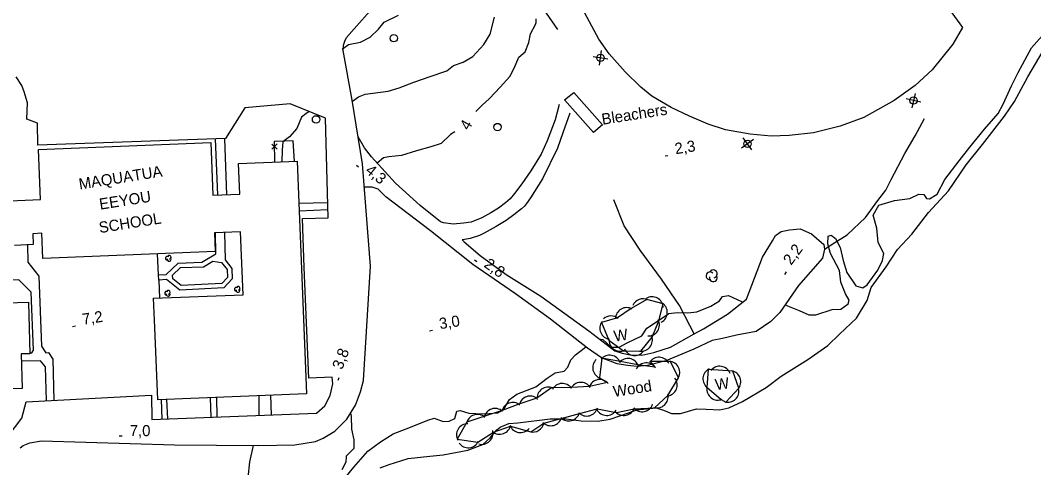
# Model space of a CAD drawing. Extents: x 646142 to 649934, y 5874075 to 5876351.
# Drawn here: x 647111.3 to 647384.4, y 5874421.5 to 5874542.2 of the extents above; entities that cross this region are included whole.
import ezdxf

# ---------------------------------------------------------------- set-up
doc = ezdxf.new("R2010")
doc.units = 0
for name, color, linetype in [('Niveau 19', 7, 'Continuous'), ('Niveau 2', 7, 'Continuous'), ('Niveau 22', 7, 'Continuous'), ('Niveau 3', 7, 'Continuous'), ('Niveau 31', 7, 'Continuous'), ('Niveau 36', 7, 'Continuous'), ('Niveau 37', 7, 'Continuous'), ('Niveau 4', 7, 'Continuous'), ('Niveau 44', 7, 'Continuous'), ('Niveau 56', 7, 'Continuous')]:
    doc.layers.add(name, color=color, linetype=linetype)

msp = doc.modelspace()

# ---------------------------------------------------------------- linework, layer by layer
at = {"layer": 'Niveau 19'}
for points in [[(647111.21, 5874426.85), (647112.01, 5874427.53), (647113.89, 5874428.24), (647116.95, 5874428.79), (647152.82, 5874427.71), (647175.49, 5874427.53), (647185.24, 5874427.7), (647190.8, 5874428.64), (647192.85, 5874429.47), (647196.05, 5874431.41), (647199.29, 5874434.63), (647201.59, 5874438.42), (647202.93, 5874442), (647203.75, 5874445.03), (647205.62, 5874475.91), (647203.48, 5874503.48), (647200.68, 5874520.68), (647198.25, 5874534.01), (647198.37, 5874535.49), (647198.72, 5874536.6), (647199.2, 5874537.54), (647208.24, 5874547.87)], [(647108, 5874430.06), (647111.68, 5874434.89), (647112.83, 5874439.28), (647146.62, 5874441.13), (647146.76, 5874434.51), (647191.12, 5874436.23), (647193.33, 5874438.25), (647194.77, 5874440.96), (647195.48, 5874444.13), (647195.31, 5874445.97), (647189.03, 5874445.68), (647187.8, 5874475.49), (647187.33, 5874488.7), (647194.2, 5874488.92), (647193.55, 5874515.82), (647184.02, 5874519.69), (647171.75, 5874518.55), (647166.58, 5874510.28), (647116.05, 5874508.52), (647115.9, 5874514.41), (647113.04, 5874515.54), (647113.2, 5874519.95), (647112.33, 5874522.88), (647111.68, 5874524.61), (647110.14, 5874526.97)], [(647256.44, 5874519.47), (647255.4, 5874515.38), (647253.28, 5874509.64), (647251.63, 5874506.12), (647248.83, 5874501.63), (647246.41, 5874498.06), (647244.46, 5874495.48), (647243.26, 5874494.02), (647242.01, 5874492.94), (647240.17, 5874491.5), (647238.07, 5874490.23), (647235.63, 5874488.96), (647232.73, 5874487.79), (647230.66, 5874487.45), (647227.95, 5874487.23), (647225.31, 5874487.61), (647224.5, 5874487.81), (647219.02, 5874492.21), (647212.38, 5874498.3), (647205.88, 5874505.35), (647204.05, 5874507.77), (647202.29, 5874510.8)], [(647259.34, 5874517.1), (647257.48, 5874511.86), (647256.06, 5874507.73), (647251.99, 5874499.41), (647248.76, 5874494.33), (647247.67, 5874492.78), (647247.12, 5874492.08), (647246.37, 5874491.36), (647244.26, 5874489.69), (647242.24, 5874488.18), (647239.54, 5874486.54), (647236.28, 5874484.74), (647235.02, 5874484.15), (647232.53, 5874483.32), (647230.94, 5874483.09), (647230.37, 5874482.97), (647230.91, 5874482.41), (647235.16, 5874478.77), (647242.19, 5874473.66), (647251.54, 5874467.82), (647258.05, 5874463.13), (647264.45, 5874458.42), (647271.51, 5874453.07), (647273.47, 5874452.43), (647275.65, 5874451.94), (647278.74, 5874451.88), (647282, 5874452.56), (647286.47, 5874454.07), (647292.88, 5874457.61), (647295.35, 5874458.97), (647301.83, 5874462.93), (647307, 5874467), (647311.31, 5874478.33)], [(647311.31, 5874478.33), (647313.94, 5874482.75), (647314.76, 5874484.12), (647316.31, 5874485.22), (647318.52, 5874485.68), (647321.45, 5874485.96), (647324.44, 5874484.6), (647327.81, 5874481.73), (647327.94, 5874480.44), (647327.47, 5874478.02), (647320.98, 5874470.63), (647315.9, 5874463.37), (647313.53, 5874461), (647309.54, 5874458.23), (647304.3, 5874457.24), (647300.47, 5874456.39), (647297.67, 5874455.88), (647292.81, 5874453.5), (647285.18, 5874450.38), (647280.32, 5874449.07), (647277.51, 5874448.79), (647274.86, 5874449.13), (647272.09, 5874449.57), (647267.9, 5874451.17), (647264.08, 5874453.76), (647254.17, 5874461.56), (647244.71, 5874468.45), (647233.26, 5874476.33), (647221.82, 5874485.39), (647209.77, 5874494.62), (647207.67, 5874496.66), (647206.08, 5874497.21), (647205.62, 5874497.17), (647203.97, 5874497.17)]]:
    msp.add_lwpolyline(points, dxfattribs=at)
at = {"layer": 'Niveau 2'}
for points in [[(647198.03, 5874534.4), (647199.69, 5874535.62), (647202.98, 5874536.3), (647205.56, 5874537.61), (647207.76, 5874539.83), (647209.34, 5874541.64), (647213.16, 5874543.6)], [(647200.82, 5874520.38), (647202.41, 5874521.55), (647204.2, 5874522.28), (647210.41, 5874523.08), (647213.41, 5874523.97), (647217.29, 5874525.52), (647221.75, 5874526.99), (647226.2, 5874528.53), (647228, 5874530.02), (647230.65, 5874530.94), (647233.2, 5874532.38), (647236.17, 5874535.66), (647237.92, 5874538.44), (647239.05, 5874543.03)], [(647234.03, 5874517.58), (647235.6, 5874519.24), (647237.69, 5874521.13), (647240.61, 5874524.11), (647243.22, 5874527.03), (647244.36, 5874529.27), (647245.6, 5874532.2), (647247.32, 5874533.67), (647248.31, 5874536.16), (647248.76, 5874538.53), (647250.09, 5874541.06), (647250.27, 5874541.62), (647250.26, 5874542.55)], [(647317.4, 5874465.51), (647318.02, 5874465.22), (647321.17, 5874463.93), (647323.78, 5874462.76), (647325.68, 5874462.77), (647330.04, 5874464.21), (647332.41, 5874464.26), (647334.34, 5874465.7), (647334.65, 5874466.74), (647333.65, 5874468.42), (647332.38, 5874471.56), (647332, 5874474.72), (647329.59, 5874479.28), (647328.84, 5874481.94), (647328.94, 5874483.96), (647329.74, 5874484.28), (647330.96, 5874483.33), (647332.21, 5874480.91), (647332.98, 5874477.42), (647334.01, 5874474.21), (647336.39, 5874470.59), (647338.29, 5874470.06), (647339.51, 5874470.89), (647342.31, 5874474.84), (647343.59, 5874477.4), (647343.99, 5874479.34), (647342.45, 5874482.27), (647342.06, 5874486.14), (647341.12, 5874489.61), (647342.62, 5874492.36), (647346.88, 5874493.61), (647350.98, 5874494.13), (647353.35, 5874495.31), (647354.78, 5874495.22), (647355.43, 5874494.1), (647356.27, 5874494), (647358.33, 5874495.27), (647360.42, 5874499.27), (647364.3, 5874504.27), (647367.13, 5874507.93), (647371.08, 5874512.82), (647374.74, 5874517.09), (647376.15, 5874519.54), (647378.37, 5874524.49), (647380.2, 5874528.11), (647383.73, 5874534.79), (647388.15, 5874539.73)], [(647189.15, 5874517.61), (647188.21, 5874516.93), (647187.07, 5874516.02), (647185.81, 5874512.99), (647183.85, 5874510.72), (647181.98, 5874509.4), (647181.82, 5874507.16), (647181.79, 5874504)], [(647228.4, 5874512.14), (647227.21, 5874511.38), (647224.64, 5874508.94), (647221.9, 5874508.02), (647218.07, 5874506.94), (647213.99, 5874505.71), (647210.57, 5874505.34), (647209.14, 5874505.08), (647207.46, 5874503.64)], [(647267.3, 5874456.26), (647268.29, 5874456.06), (647270.5, 5874454.08), (647272.65, 5874454), (647274.78, 5874455.21), (647278.74, 5874457.09), (647280.14, 5874459.12), (647282.47, 5874460.71), (647286.03, 5874463.08), (647288.25, 5874463.42), (647291.17, 5874463.29), (647293.57, 5874463.59), (647297.39, 5874465.09), (647299.68, 5874466.56), (647300.51, 5874467.71), (647302.08, 5874467.98), (647305.62, 5874466.37), (647306, 5874466.21)], [(647198.85, 5874418.77), (647201.17, 5874421.72), (647204.96, 5874425.97), (647208.3, 5874428.53), (647211.74, 5874430.64), (647216.41, 5874432.49), (647221.09, 5874434.35), (647222.79, 5874434.9), (647225.2, 5874433.98), (647226.88, 5874434.06), (647228.39, 5874434.78), (647228.93, 5874436.76), (647229.79, 5874436.95), (647232.12, 5874436.2), (647234.04, 5874436.12), (647236.45, 5874436.08), (647239.87, 5874436.36), (647241.55, 5874437.36), (647243.13, 5874439.88), (647245.07, 5874441.32), (647250.2, 5874443.31), (647253.29, 5874445.69), (647255.37, 5874447.08), (647257.81, 5874447.55), (647258.83, 5874448.6), (647259.65, 5874450.58), (647260.87, 5874451.95), (647263.24, 5874453.78), (647263.64, 5874454.11)], [(647200.28, 5874436.27), (647200.43, 5874435.41), (647200.54, 5874431.92), (647201.18, 5874429.08), (647201.18, 5874426.71), (647199.08, 5874424.61), (647199, 5874423), (647197.96, 5874420.95)], [(647172.66, 5874418.84), (647173.12, 5874423.15), (647174.14, 5874427.54)]]:
    msp.add_lwpolyline(points, dxfattribs=at)
at = {"layer": 'Niveau 22'}
for points in [[(647327.94, 5874480.44), (647330.72, 5874482.25), (647334.07, 5874484.36), (647339.05, 5874489), (647342.38, 5874493.59), (647344.47, 5874496.41), (647345.96, 5874499.28), (647349.64, 5874506.28), (647352.36, 5874511.04), (647354.94, 5874515.73)], [(647164.49, 5874495.05), (647163.89, 5874510.18)], [(647166.27, 5874510.27), (647166.84, 5874495.15)], [(647186.35, 5874492.87), (647194.1, 5874493.03)], [(647186.43, 5874490.83), (647194.15, 5874491.15)], [(647292.88, 5874457.61), (647291.71, 5874459.87), (647288.91, 5874465.28), (647284.05, 5874472.39), (647278.28, 5874480.24), (647273.95, 5874486.8), (647271.24, 5874493.76)], [(647166.28, 5874485), (647166.51, 5874477.6), (647168.29, 5874475.28), (647168.38, 5874472.45), (647166.13, 5874470), (647154.25, 5874469.39), (647150.7, 5874472.29), (647148.62, 5874472.14), (647148.55, 5874473.5), (647150.59, 5874473.64), (647153.79, 5874476.7), (647160.24, 5874476.97), (647163.99, 5874479.17), (647163.84, 5874484.91)], [(647113.22, 5874481.62), (647113.33, 5874476.94), (647116.26, 5874473.19), (647116.96, 5874454.28), (647118.15, 5874452.47), (647118.92, 5874452.56), (647120.09, 5874450.84), (647120.32, 5874439.69)], [(647152.31, 5874473.46), (647154.41, 5874475.49), (647160.67, 5874475.74), (647163.18, 5874477.27), (647165.54, 5874476.84), (647166.99, 5874474.94), (647167.11, 5874472.85), (647165.62, 5874471.21), (647154.65, 5874470.71), (647152.37, 5874472.47), (647152.31, 5874473.46), (647152.31, 5874473.46)], [(647113.87, 5874452.55), (647114.42, 5874452.47), (647114.82, 5874453.2), (647114.25, 5874468.91), (647110.93, 5874472.23), (647103.7, 5874471.97), (647102.45, 5874470.99), (647102.54, 5874465.84)], [(647118.32, 5874439.58), (647118.03, 5874448.73), (647116.68, 5874450.32), (647111.56, 5874450.23)], [(647149.2, 5874439.88), (647149.38, 5874434.61)], [(647150.69, 5874439.94), (647150.92, 5874434.67)], [(647162.43, 5874440.41), (647162.62, 5874435.13)], [(647164.15, 5874440.48), (647164.23, 5874435.19)], [(647175.59, 5874440.94), (647175.58, 5874435.63)], [(647178.74, 5874441.07), (647178.92, 5874435.76)]]:
    msp.add_lwpolyline(points, dxfattribs=at)
at = {"layer": 'Niveau 3'}
for p, q in [((647285.01, 5874505.64), (647285.8, 5874505.77)), ((647201.83, 5874503.13), (647202.45, 5874502.63)), ((647233.66, 5874477.56), (647234.31, 5874477.1)), ((647317.26, 5874473.66), (647317.73, 5874474.31)), ((647125.34, 5874459.64), (647126.13, 5874459.77)), ((647221.53, 5874458.45), (647222.32, 5874458.58)), ((647196.96, 5874445.12), (647197.24, 5874445.86)), ((647137.89, 5874430.09), (647138.69, 5874430.09))]:
    msp.add_line(p, q, dxfattribs=at)
at = {"layer": 'Niveau 31'}
for points in [[(647106.39, 5874493.42), (647116.72, 5874493.83), (647116.18, 5874507.35), (647162.62, 5874509.21), (647163.19, 5874495), (647170.4, 5874495.29), (647170.07, 5874503.53), (647185.9, 5874504.16)], [(647185.9, 5874504.16), (647188.41, 5874441.45), (647148.3, 5874439.85), (647147.52, 5874459.34), (647147.2, 5874467.22), (647171.31, 5874468.18), (647170.63, 5874485.18), (647163.63, 5874484.9), (647163.83, 5874479.83), (647117.34, 5874477.97), (647117.06, 5874484.74), (647114.64, 5874484.64), (647114.76, 5874481.68), (647109.68, 5874481.48)], [(647089.62, 5874465.47), (647113.48, 5874466.15), (647113.88, 5874452.28), (647111.51, 5874452.21), (647111.77, 5874442.92), (647092.63, 5874442.37), (647092.37, 5874451.58), (647090.02, 5874451.51), (647089.62, 5874465.47)]]:
    msp.add_lwpolyline(points, dxfattribs=at)
at = {"layer": 'Niveau 36'}
for p, q in [((647269.58, 5874531.74), (647265.64, 5874532.36)), ((647267.31, 5874530.08), (647267.92, 5874534.02)), ((647352.42, 5874522.48), (647351.49, 5874518.6)), ((647353.89, 5874520.07), (647350.01, 5874521)), ((647308.4, 5874507.25), (647306.05, 5874510.48)), ((647308.84, 5874510.04), (647305.61, 5874507.7))]:
    msp.add_line(p, q, dxfattribs=at)
for centre in [(647211.91, 5874537.35), (647267.61, 5874532.06), (647351.95, 5874520.54), (647190.98, 5874515.46), (647239.85, 5874513.39), (647307.22, 5874508.87)]:
    msp.add_circle(centre, 1, dxfattribs=at)
at = {"layer": 'Niveau 37'}
for points in [[(647179.03, 5874508.82), (647180.46, 5874507.41)], [(647179.05, 5874507.4), (647180.45, 5874508.83)], [(647185.19, 5874504.14), (647184.84, 5874509.67), (647179.73, 5874509.46), (647179.79, 5874503.92)], [(647185.19, 5874504.14), (647184.84, 5874509.67), (647179.73, 5874509.46), (647179.79, 5874503.92)], [(647185.19, 5874504.14), (647184.84, 5874509.67), (647179.73, 5874509.46), (647179.79, 5874503.92)], [(647185.19, 5874504.14), (647184.84, 5874509.67), (647180.38, 5874509.49)], [(647179.77, 5874506.11), (647179.79, 5874503.92)], [(647148.55, 5874473.5), (647148.26, 5874479.21)], [(647148.55, 5874473.5), (647148.26, 5874479.21)], [(647148.62, 5874472.14), (647148.83, 5874467.28)], [(647148.62, 5874472.14), (647148.83, 5874467.28)]]:
    msp.add_lwpolyline(points, dxfattribs=at)
at = {"layer": 'Niveau 4'}
for points in [[(647256.14, 5874539.7), (647249.23, 5874549.77)], [(647302.2, 5874437.69), (647305.84, 5874439.36), (647312.22, 5874443.2), (647316.31, 5874446.21), (647323.46, 5874450.72), (647328.91, 5874454.46), (647332.05, 5874457.5), (647336.6, 5874461.87), (647339.44, 5874466.66), (647340.52, 5874470.09), (647344.58, 5874475.72), (647347.67, 5874480.41), (647351.54, 5874484.47), (647356.04, 5874490.38), (647361.39, 5874496.24), (647366.14, 5874503.24), (647370.58, 5874508.66), (647376.45, 5874516.35), (647379.14, 5874520.3), (647382.74, 5874526.94), (647386.89, 5874533.99)], [(647208.26, 5874421.52), (647210.63, 5874422.42), (647215.75, 5874424.02), (647221.64, 5874424.62), (647225.22, 5874425.04), (647231.88, 5874426.3), (647235.95, 5874427.81), (647237.9, 5874429.62), (647239.71, 5874431.76), (647240.58, 5874432.42), (647242.95, 5874433.44), (647245.38, 5874433.64), (647254.03, 5874434.71), (647258.34, 5874434.72), (647262.4, 5874434.14), (647266.92, 5874434.1), (647270.19, 5874434.66), (647277.54, 5874437.17), (647282.6, 5874437.67), (647284.57, 5874437.03), (647286.79, 5874436.18), (647289.17, 5874436.17), (647293.44, 5874437.43), (647296.06, 5874437.33), (647299.77, 5874437.1), (647302.2, 5874437.69)]]:
    msp.add_lwpolyline(points, dxfattribs=at)
at = {"layer": 'Niveau 44'}
for points in [[(647267.86, 5874460.67), (647269.87, 5874455.93), (647273.8, 5874453.09), (647278.45, 5874452.96), (647281.52, 5874456.72), (647283.3, 5874461.16), (647284.49, 5874465.76), (647280.09, 5874466.9), (647275.87, 5874464.47), (647272.17, 5874461.92), (647267.86, 5874460.67)], [(647282.28, 5874448.65), (647277.69, 5874449.31), (647272.91, 5874450.16), (647267.98, 5874451.03), (647267.34, 5874445.74), (647269.51, 5874444.48), (647264.64, 5874443.45), (647259.79, 5874443.16), (647254.4, 5874443.11), (647250.49, 5874440.24), (647245.65, 5874438.63), (647241.1, 5874436.95), (647236.21, 5874435.35), (647231.62, 5874433.78), (647229.04, 5874429.24), (647234.55, 5874428.39), (647238.77, 5874431.08), (647243.34, 5874432.72), (647248.89, 5874431.19), (647252.34, 5874433.51), (647257.03, 5874434.78), (647262, 5874436.11), (647266.68, 5874437.38), (647271.9, 5874436.39), (647276.65, 5874437.38), (647282.21, 5874437.71), (647285.8, 5874440.98), (647288.62, 5874445.81), (647286.5, 5874450.17), (647281.03, 5874450.21), (647282.28, 5874448.65)], [(647301.4, 5874439.24), (647304.9, 5874443.02), (647303.26, 5874447.59), (647296.64, 5874448.05), (647296.28, 5874443.21), (647300.14, 5874439.9), (647301.4, 5874439.24)]]:
    msp.add_lwpolyline(points, dxfattribs=at)
for centre, radius, start, end in [((647150.93, 5874478), 0.523, 44.1154, 269.804), ((647151.38, 5874477.73), 0.523, 166.9369, 29.6212), ((647151.38, 5874478.26), 0.523, 282.2692, 149.7263), ((647298.02, 5874473.8), 1.05, 282.2692, 149.7263), ((647297.12, 5874473.27), 1.05, 44.1154, 269.804), ((647298.02, 5874472.75), 1.05, 166.9369, 29.6212), ((647151.14, 5874468.83), 0.523, 282.2692, 149.7263), ((647169.51, 5874469.63), 0.523, 44.1154, 269.804), ((647169.96, 5874469.37), 0.523, 166.9369, 29.6212), ((647169.96, 5874469.89), 0.523, 282.2692, 149.7263), ((647150.69, 5874468.57), 0.523, 44.1154, 269.804), ((647151.14, 5874468.31), 0.523, 166.9369, 29.6212), ((647279.09, 5874464.07), 3, 64.6343, 156.539), ((647281.52, 5874464.62), 3, 1.8104, 121.7884), ((647274.67, 5874461.71), 3, 60.4815, 180.4594), ((647282.62, 5874463.41), 3, 297.5642, 57.5422), ((647270.45, 5874459.46), 3, 49.078, 133.0016), ((647280.51, 5874460.06), 3, 267.4774, 27.4553), ((647270.43, 5874459.13), 3, 142.9645, 262.9424), ((647272.87, 5874455.94), 3, 174.1817, 294.1597), ((647278.62, 5874455.95), 3, 260.7354, 20.7133), ((647276.83, 5874454.77), 3, 202.5523, 322.5302), ((647268.51, 5874448.5), 3, 133.1586, 253.1366), ((647270.07, 5874448.87), 3, 19.9654, 139.9434), ((647274.99, 5874448), 3, 19.9654, 139.9434), ((647283.36, 5874448.32), 3, 26.8952, 146.8731), ((647285.98, 5874447.22), 3, 325.9528, 85.9307), ((647279.92, 5874446.79), 3, 32.274, 152.252), ((647298.22, 5874445.5), 3, 115.7382, 235.7161), ((647299.74, 5874445.89), 3, 21.0403, 141.0183), ((647302.42, 5874444.71), 3, 319.782, 79.7599), ((647267.43, 5874442.32), 3, 40.0413, 160.0192), ((647285.29, 5874443.85), 3, 277.4086, 37.3866), ((647253.49, 5874440.25), 3, 66.3194, 186.2974), ((647257.33, 5874441.25), 3, 33.4377, 153.4157), ((647262.32, 5874441.55), 3, 33.4377, 153.4157), ((647299.25, 5874442.76), 3, 173.4084, 293.3863), ((647301.92, 5874442.19), 3, 253.9837, 13.9616), ((647248.68, 5874437.87), 3, 50.2705, 170.2484), ((647282.82, 5874440.65), 3, 252.3191, 12.2971), ((647239.22, 5874434.51), 3, 48.8229, 168.8008), ((647243.98, 5874436.14), 3, 50.2705, 170.2484), ((647263.88, 5874438.45), 3, 225.1085, 345.0864), ((647269.28, 5874438.62), 3, 208.313, 328.2909), ((647273.91, 5874438.61), 3, 221.7592, 341.7372), ((647278.81, 5874439.63), 3, 221.7592, 341.7372), ((647234.48, 5874432.9), 3, 48.8229, 168.8008), ((647254.22, 5874435.85), 3, 225.1085, 345.0864), ((647259.05, 5874437.15), 3, 225.1085, 345.0864), ((647231.81, 5874430.4), 3, 88.6405, 208.6185), ((647235.66, 5874430.83), 3, 253.7251, 13.703), ((647240.46, 5874433.56), 3, 229.6863, 349.6642), ((647246.03, 5874434.02), 3, 200.963, 320.941), ((647249.39, 5874434.15), 3, 254.4173, 349.9616), ((647231.96, 5874429.91), 3, 215.6402, 335.6182)]:
    msp.add_arc(centre, radius, start, end, dxfattribs=at)
at = {"layer": 'Niveau 56'}
for points in [[(647338.94, 5874576.47), (647365.19, 5874540.24), (647362.58, 5874535.72), (647357.02, 5874528.79), (647352.42, 5874524.63), (647346.73, 5874520.53), (647338.55, 5874515.95), (647332.16, 5874513.64), (647325.03, 5874511.82), (647318.45, 5874511.15), (647313.57, 5874510.97), (647307.93, 5874511.49), (647301.33, 5874512.68), (647296.65, 5874514.19), (647291.61, 5874516.34), (647286.63, 5874518.7), (647281.48, 5874521.72), (647278.46, 5874524.11), (647274.25, 5874528.32), (647269.98, 5874533.11), (647267.16, 5874537.1), (647263.41, 5874544.1)], [(647265.73, 5874511.89), (647257.9, 5874520.78), (647260.43, 5874522.72), (647268.16, 5874514), (647265.73, 5874511.89)]]:
    msp.add_lwpolyline(points, dxfattribs=at)

# ---------------------------------------------------------------- texts
at = {"layer": 'Niveau 2'}
msp.add_text('4', height=3, rotation=60.5507, dxfattribs=at).set_placement((647232.11, 5874512.3))
at = {"layer": 'Niveau 3'}
for s, rotation, p in [('2,3  ', 8.9405, (647287.86, 5874506.05)), ('4,3  ', 320.7806, (647204.03, 5874501.28)), ('2,2  ', 53.941, (647318.99, 5874475.96)), ('2,8  ', 324.4431, (647235.98, 5874475.85)), ('7,2  ', 8.9405, (647128.2, 5874460.05)), ('3,0  ', 8.941, (647224.38, 5874458.86)), ('3,8  ', 69.4022, (647198.01, 5874447.8)), ('7,0  ', 359.8507, (647140.77, 5874430.04))]:
    msp.add_text(s, height=3, rotation=rotation, dxfattribs=at).set_placement(p)
at = {"layer": 'Niveau 31'}
for s, p in [('MAQUATUA', (647127.28, 5874496.54)), ('EEYOU', (647132.8, 5874491.1)), ('SCHOOL', (647132.7, 5874484.78))]:
    msp.add_text(s, height=3, rotation=8.941, dxfattribs=at).set_placement(p)
at = {"layer": 'Niveau 44'}
for s, p in [('W', (647271.44, 5874455.5)), ('Wood', (647271.26, 5874440.58)), ('W', (647298.75, 5874442.4))]:
    msp.add_text(s, height=3, rotation=8.9405, dxfattribs=at).set_placement(p)
at = {"layer": 'Niveau 56'}
msp.add_text('Bleachers', height=3, rotation=8.9405, dxfattribs=at).set_placement((647268.16, 5874514))

doc.saveas('drawing.dxf')
